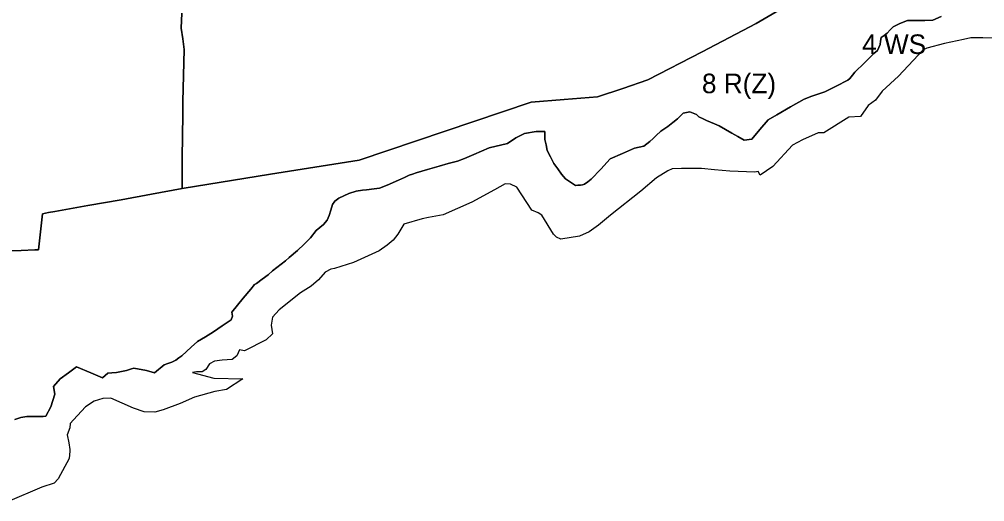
# Model space of a CAD drawing. Extents: x 7423432 to 7425824, y 5537848 to 5539677.
# Drawn here: x 7424610 to 7425103.3, y 5537960.2 to 5538206.4 of the extents above; entities that cross this region are included whole.
import ezdxf

# ---------------------------------------------------------------- set-up
doc = ezdxf.new("R2010")
doc.units = 0
doc.layers.add('linie_rozgraniczajace', color=7, linetype='Continuous')
doc.layers.add('oznaczenia_przeznaczen', color=7, linetype='Continuous')

msp = doc.modelspace()

# ---------------------------------------------------------------- linework, layer by layer
at = {"layer": 'linie_rozgraniczajace'}
for points in [[(7424603.87, 5538088.22), (7424610.91, 5538088.47), (7424617.95, 5538088.72), (7424619.77, 5538088.79), (7424620.78, 5538097.98), (7424621.79, 5538107.17), (7424624.97, 5538107.74), (7424628.14, 5538108.31), (7424645.06, 5538111.34), (7424661.98, 5538114.37), (7424677.56, 5538117.23), (7424693.14, 5538120.08), (7424738.41, 5538127.34), (7424783.68, 5538134.59), (7424827.56, 5538149.39), (7424871.49, 5538164.19), (7424888.47, 5538165.51), (7424905.46, 5538166.82), (7424918.29, 5538171.17), (7424931.13, 5538175.51), (7424958.85, 5538189.9), (7424986.57, 5538204.28), (7425000.82, 5538212.65)], [(7424693.12, 5538209.54), (7424692.72, 5538201.94), (7424693.5, 5538196.44), (7424694.29, 5538190.94), (7424693.94, 5538177.67), (7424693.59, 5538164.41), (7424693.49, 5538156.36), (7424693.39, 5538148.31), (7424693.26, 5538134.2), (7424693.14, 5538120.08), (7424677.56, 5538117.23), (7424661.98, 5538114.37), (7424645.06, 5538111.34), (7424628.14, 5538108.31), (7424624.97, 5538107.74), (7424621.79, 5538107.17), (7424620.78, 5538097.98), (7424619.77, 5538088.79), (7424617.95, 5538088.72), (7424610.91, 5538088.47), (7424603.87, 5538088.22)], [(7425000.82, 5538212.65), (7424986.57, 5538204.28), (7424958.85, 5538189.9), (7424931.13, 5538175.51), (7424918.29, 5538171.17), (7424905.46, 5538166.82), (7424888.47, 5538165.51), (7424871.49, 5538164.19), (7424827.56, 5538149.39), (7424783.68, 5538134.59), (7424738.41, 5538127.34), (7424693.14, 5538120.08), (7424693.26, 5538134.2), (7424693.39, 5538148.31), (7424693.49, 5538156.36), (7424693.59, 5538164.41), (7424693.94, 5538177.67), (7424694.29, 5538190.94), (7424693.5, 5538196.44), (7424692.72, 5538201.94), (7424693.12, 5538209.54)], [(7424824.55, 5538131.51), (7424829.21, 5538132.76), (7424833.88, 5538134), (7424837.47, 5538135.34), (7424842.19, 5538137.38), (7424850.04, 5538140.76), (7424859.37, 5538142.98), (7424863.68, 5538145.88), (7424868.17, 5538148.12), (7424874.06, 5538149.08), (7424878.45, 5538149.08), (7424878.51, 5538145.1), (7424879.14, 5538142.3), (7424879.78, 5538139.49), (7424881.47, 5538136.18), (7424883.16, 5538132.86), (7424885.14, 5538130.11), (7424887.12, 5538127.35), (7424889.13, 5538125.02), (7424891.69, 5538123.35), (7424894.24, 5538121.67), (7424895.46, 5538121.69), (7424896.67, 5538121.7), (7424897.69, 5538121.97), (7424898.71, 5538122.24), (7424900.49, 5538123.55), (7424902.26, 5538124.86), (7424907.05, 5538129.99), (7424911.84, 5538135.13), (7424918.12, 5538137.86), (7424924.4, 5538140.6), (7424926.79, 5538141.11), (7424929.19, 5538141.63), (7424932.24, 5538144.05), (7424933.86, 5538145.6), (7424935.48, 5538147.15), (7424937.84, 5538149.26), (7424941.42, 5538151.75), (7424943.9, 5538153.72), (7424946.37, 5538155.69), (7424946.81, 5538156.14), (7424949.16, 5538158.57), (7424952.59, 5538159.27), (7424956.04, 5538157.78), (7424957.22, 5538156.73), (7424959.43, 5538155.58), (7424961.16, 5538154.86), (7424965.26, 5538153.13), (7424967.61, 5538152.11), (7424974.01, 5538148.31), (7424977.16, 5538146.56), (7424980.31, 5538144.8), (7424984.21, 5538145.31), (7424988.45, 5538150.18), (7424992.69, 5538155.04), (7424997.06, 5538157.72), (7425004.04, 5538161.7), (7425011.02, 5538165.68), (7425015.03, 5538167.14), (7425019.04, 5538168.59), (7425021.58, 5538169.41), (7425027.4, 5538172.38), (7425033.27, 5538175.39), (7425034.33, 5538176.26), (7425035.69, 5538177.88), (7425037, 5538179.45), (7425041.82, 5538184.18), (7425046.64, 5538188.92), (7425048.42, 5538190.47), (7425049.15, 5538192.03), (7425049.88, 5538193.59), (7425050.09, 5538195.33), (7425050.3, 5538197.07), (7425051.9, 5538198.21), (7425053.49, 5538199.34), (7425055.01, 5538201), (7425056.53, 5538202.66), (7425059.96, 5538204.23), (7425063.83, 5538205.88), (7425068.7, 5538205.76), (7425072.69, 5538205.85), (7425076.69, 5538205.94), (7425081.1, 5538207.82)], [(7425081.1, 5538207.82), (7425076.69, 5538205.94), (7425072.69, 5538205.85), (7425068.7, 5538205.76), (7425063.83, 5538205.88), (7425059.96, 5538204.23), (7425056.53, 5538202.66), (7425055.01, 5538201), (7425053.49, 5538199.34), (7425051.9, 5538198.21), (7425050.3, 5538197.07), (7425050.09, 5538195.33), (7425049.88, 5538193.59), (7425049.15, 5538192.03)], [(7425109.59, 5538196.81), (7425102.38, 5538196.97), (7425096.27, 5538196.94), (7425092.51, 5538196.15), (7425082.74, 5538194.13), (7425073.77, 5538191.62), (7425071.78, 5538190.82), (7425059.31, 5538177.47), (7425050.91, 5538169.7), (7425047.5, 5538165.18), (7425043.78, 5538162.35), (7425039.74, 5538156.86), (7425033.93, 5538156.43), (7425021.01, 5538148.5), (7425018.15, 5538148.49), (7425010.14, 5538144.92), (7425005.01, 5538142.12), (7424995.09, 5538131.27), (7424988.52, 5538126.9)], [(7425049.15, 5538192.03), (7425048.42, 5538190.47), (7425046.64, 5538188.92), (7425041.82, 5538184.18), (7425037, 5538179.45), (7425035.69, 5538177.88), (7425034.33, 5538176.26), (7425033.27, 5538175.39), (7425027.4, 5538172.38), (7425021.58, 5538169.41), (7425019.04, 5538168.59), (7425015.03, 5538167.14), (7425011.02, 5538165.68), (7425004.04, 5538161.7), (7424997.06, 5538157.72), (7424992.69, 5538155.04), (7424988.45, 5538150.18), (7424984.21, 5538145.31), (7424980.31, 5538144.8), (7424977.16, 5538146.56), (7424974.01, 5538148.31), (7424967.61, 5538152.11), (7424965.26, 5538153.13), (7424961.16, 5538154.86), (7424959.43, 5538155.58), (7424957.22, 5538156.73), (7424956.04, 5538157.78), (7424952.59, 5538159.27), (7424949.16, 5538158.57), (7424946.81, 5538156.14), (7424946.37, 5538155.69), (7424943.9, 5538153.72), (7424941.42, 5538151.75), (7424937.84, 5538149.26), (7424935.48, 5538147.15), (7424933.86, 5538145.6), (7424932.24, 5538144.05), (7424929.19, 5538141.63), (7424926.79, 5538141.11), (7424924.4, 5538140.6), (7424918.12, 5538137.86), (7424911.84, 5538135.13), (7424907.05, 5538129.99), (7424902.26, 5538124.86), (7424900.49, 5538123.55), (7424898.71, 5538122.24), (7424897.69, 5538121.97), (7424896.67, 5538121.7), (7424895.46, 5538121.69), (7424894.24, 5538121.67), (7424891.69, 5538123.35), (7424889.13, 5538125.02), (7424887.12, 5538127.35), (7424885.14, 5538130.11), (7424883.16, 5538132.86), (7424881.47, 5538136.18), (7424879.78, 5538139.49), (7424879.14, 5538142.3), (7424878.51, 5538145.1), (7424878.45, 5538149.08), (7424874.06, 5538149.08), (7424868.17, 5538148.12), (7424863.68, 5538145.88), (7424859.37, 5538142.98), (7424850.04, 5538140.76), (7424842.19, 5538137.38), (7424837.47, 5538135.34), (7424833.88, 5538134), (7424829.21, 5538132.76), (7424824.55, 5538131.51), (7424818.64, 5538129.81), (7424812.74, 5538128.1), (7424810.95, 5538127.47), (7424809.17, 5538126.85), (7424806.8, 5538125.73), (7424803.76, 5538124.32), (7424797.89, 5538121.72), (7424794.01, 5538120.18), (7424791.32, 5538119.9), (7424787.41, 5538119.45), (7424785.3, 5538119.22), (7424782.12, 5538118.68), (7424778.29, 5538117.54), (7424775.77, 5538116.3), (7424773.26, 5538115.06), (7424771.16, 5538113.62), (7424770, 5538111.85), (7424769.19, 5538109.03), (7424768.38, 5538106.22), (7424767.38, 5538103.88), (7424765.48, 5538101.69), (7424761.74, 5538098.61), (7424758.85, 5538094.91), (7424755.49, 5538091.71), (7424752.12, 5538088.51), (7424747.91, 5538084.89), (7424746.09, 5538083.19), (7424743.82, 5538081.48), (7424741.55, 5538079.76), (7424739.41, 5538077.98)], [(7424607.73, 5538002.23), (7424610.78, 5538003.24), (7424613.79, 5538003.77), (7424618.01, 5538003.74), (7424622.23, 5538003.71), (7424623.53, 5538003.93), (7424626.07, 5538008.67), (7424628.11, 5538015.09), (7424627.46, 5538019.05), (7424630.88, 5538022.9), (7424635.06, 5538025.98), (7424639.25, 5538029.06), (7424646.55, 5538025.96), (7424652.59, 5538023.39), (7424655.2, 5538025.85), (7424657.32, 5538025.96), (7424659.69, 5538026.13), (7424662.14, 5538026.63), (7424663.07, 5538026.82), (7424664.69, 5538027.24), (7424666.3, 5538027.65), (7424667.37, 5538028.03), (7424668.44, 5538028.41), (7424674.98, 5538027.11), (7424679.03, 5538025.93), (7424683.99, 5538030.02), (7424685.97, 5538030.71), (7424687.95, 5538031.41), (7424689.9, 5538032.53), (7424691.43, 5538033.6), (7424692.97, 5538034.68), (7424697.84, 5538039.07), (7424701.12, 5538041.93), (7424705.16, 5538044.44), (7424709.21, 5538046.96), (7424713.72, 5538050), (7424718.23, 5538053.03), (7424718.9, 5538054.87), (7424718.63, 5538057.02), (7424724.41, 5538064.03), (7424728.32, 5538068.77), (7424730.23, 5538071.08), (7424731.11, 5538071.56), (7424734.13, 5538073.82), (7424737.1, 5538076.07), (7424739.41, 5538077.98), (7424741.55, 5538079.76), (7424743.82, 5538081.48), (7424746.09, 5538083.19), (7424747.91, 5538084.89), (7424752.12, 5538088.51), (7424755.49, 5538091.71), (7424758.85, 5538094.91), (7424761.74, 5538098.61), (7424765.48, 5538101.69), (7424767.38, 5538103.88), (7424768.38, 5538106.22), (7424769.19, 5538109.03), (7424770, 5538111.85), (7424771.16, 5538113.62), (7424773.26, 5538115.06), (7424775.77, 5538116.3), (7424778.29, 5538117.54), (7424782.12, 5538118.68), (7424785.3, 5538119.22), (7424787.41, 5538119.45), (7424791.32, 5538119.9), (7424794.01, 5538120.18), (7424797.89, 5538121.72), (7424803.76, 5538124.32), (7424806.8, 5538125.73), (7424809.17, 5538126.85), (7424810.95, 5538127.47), (7424812.74, 5538128.1), (7424818.64, 5538129.81), (7424824.55, 5538131.51)], [(7424988.52, 5538126.9), (7424987.57, 5538128.72), (7424985.8, 5538128.46), (7424973.05, 5538128.9), (7424965.23, 5538129.52), (7424958.62, 5538130.36), (7424948.34, 5538130.23), (7424943.59, 5538130.18), (7424941.39, 5538129.1), (7424935.64, 5538125.49), (7424927.5, 5538118.78), (7424912, 5538106.45), (7424905.91, 5538101.29), (7424901.13, 5538097.97), (7424896.18, 5538095.74), (7424886.69, 5538094.19), (7424884.47, 5538095.26), (7424883.03, 5538096.71), (7424877.03, 5538106.51), (7424875.04, 5538107.73), (7424871.95, 5538108.94), (7424864.18, 5538120.74), (7424860.91, 5538122.35), (7424858.28, 5538122.37), (7424852.76, 5538119.41), (7424841.17, 5538113.1), (7424826.53, 5538106.6), (7424819.05, 5538105.31), (7424815.79, 5538104.58), (7424806.56, 5538101.79), (7424803.46, 5538096.79), (7424801.09, 5538093.76), (7424797.9, 5538091.11), (7424793.92, 5538088.3), (7424780.68, 5538082.29), (7424771.03, 5538079.29), (7424769.14, 5538078.97), (7424766.29, 5538077.43), (7424762.81, 5538073.54), (7424759.08, 5538070.22), (7424753.7, 5538066.88), (7424742.71, 5538058.15), (7424739.42, 5538054.41), (7424738.75, 5538050.37), (7424739.32, 5538045.88), (7424736.2, 5538042.75), (7424725.11, 5538037.28), (7424722.45, 5538037.75), (7424721.15, 5538034.6), (7424718.78, 5538032.77), (7424713.58, 5538032.47), (7424709.8, 5538031.86), (7424707.23, 5538030.59), (7424705.28, 5538027.72), (7424703.51, 5538026.47), (7424700.59, 5538026.49), (7424698.54, 5538026.19), (7424709.41, 5538023.23), (7424724.14, 5538022.87), (7424715.92, 5538017.55), (7424709.94, 5538016.41), (7424699.45, 5538013.56), (7424692.27, 5538010.35), (7424683.51, 5538007.04), (7424679.23, 5538005.9), (7424673.79, 5538006.14), (7424668.37, 5538007.93), (7424656.76, 5538013), (7424652.66, 5538012.84), (7424648.2, 5538011.49), (7424643.84, 5538008.69), (7424637.71, 5538002.04), (7424635.95, 5538000.21), (7424635.76, 5537997.91), (7424634.41, 5537994.42), (7424635.26, 5537990.19), (7424635.75, 5537986.94), (7424635.89, 5537986.05), (7424635.51, 5537982.27), (7424629.77, 5537971.95), (7424627.84, 5537969.61), (7424621.48, 5537967.64), (7424603.96, 5537960.23)], [(7424739.41, 5538077.98), (7424737.1, 5538076.07), (7424734.13, 5538073.82), (7424731.11, 5538071.56), (7424730.23, 5538071.08), (7424728.32, 5538068.77), (7424724.41, 5538064.03), (7424718.63, 5538057.02), (7424718.9, 5538054.87), (7424718.23, 5538053.03), (7424713.72, 5538050), (7424709.21, 5538046.96), (7424705.16, 5538044.44), (7424701.12, 5538041.93), (7424697.84, 5538039.07), (7424692.97, 5538034.68), (7424691.43, 5538033.6), (7424689.9, 5538032.53), (7424687.95, 5538031.41), (7424685.97, 5538030.71), (7424683.99, 5538030.02), (7424679.03, 5538025.93), (7424674.98, 5538027.11), (7424668.44, 5538028.41), (7424667.37, 5538028.03), (7424666.3, 5538027.65), (7424664.69, 5538027.24), (7424663.07, 5538026.82), (7424662.14, 5538026.63), (7424659.69, 5538026.13), (7424657.32, 5538025.96), (7424655.2, 5538025.85), (7424652.59, 5538023.39), (7424646.55, 5538025.96), (7424639.25, 5538029.06), (7424635.06, 5538025.98), (7424630.88, 5538022.9), (7424627.46, 5538019.05), (7424628.11, 5538015.09), (7424626.07, 5538008.67), (7424623.53, 5538003.93), (7424622.23, 5538003.71), (7424618.01, 5538003.74), (7424613.79, 5538003.77), (7424610.78, 5538003.24), (7424607.73, 5538002.23)]]:
    msp.add_lwpolyline(points, dxfattribs=at)

# ---------------------------------------------------------------- texts
at = {"layer": 'oznaczenia_przeznaczen'}
for s, p in [('4 WS', (7425040.65, 5538188.71)), ('8 R(Z)', (7424958.8, 5538168.7))]:
    msp.add_text(s, height=10, dxfattribs=at).set_placement(p)

doc.saveas('drawing.dxf')
